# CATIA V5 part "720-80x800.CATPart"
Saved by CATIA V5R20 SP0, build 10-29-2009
Part number: 720-80x800
Definition: NONE
Nomenclature: 720-80x800
Source: Unknown
Description: 720-80x800
Bounding box of the stored display mesh (mm): x 0 to 800, y -40 to 40, z -40 to 40
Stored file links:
  C:\Users\Utente\Desktop\IO LAVORO\3D X SITO CF\X SITO\3D files 720\720-80x800.CATPart
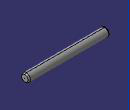
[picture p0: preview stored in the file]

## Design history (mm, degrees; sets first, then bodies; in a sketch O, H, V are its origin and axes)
Body1 "720-80x800" (main body)
  Solid1: solid without history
